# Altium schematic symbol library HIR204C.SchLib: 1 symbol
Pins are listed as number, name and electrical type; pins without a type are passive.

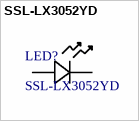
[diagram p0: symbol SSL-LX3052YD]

## SSL-LX3052YD
designator LED?
Description; Manufacturer_Name: Lumex; Type: LED Indication
footprint LED_RADIAL_SSL-LX3052YD_LUM
pins: 1 CAHTODE, 2 ANODE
